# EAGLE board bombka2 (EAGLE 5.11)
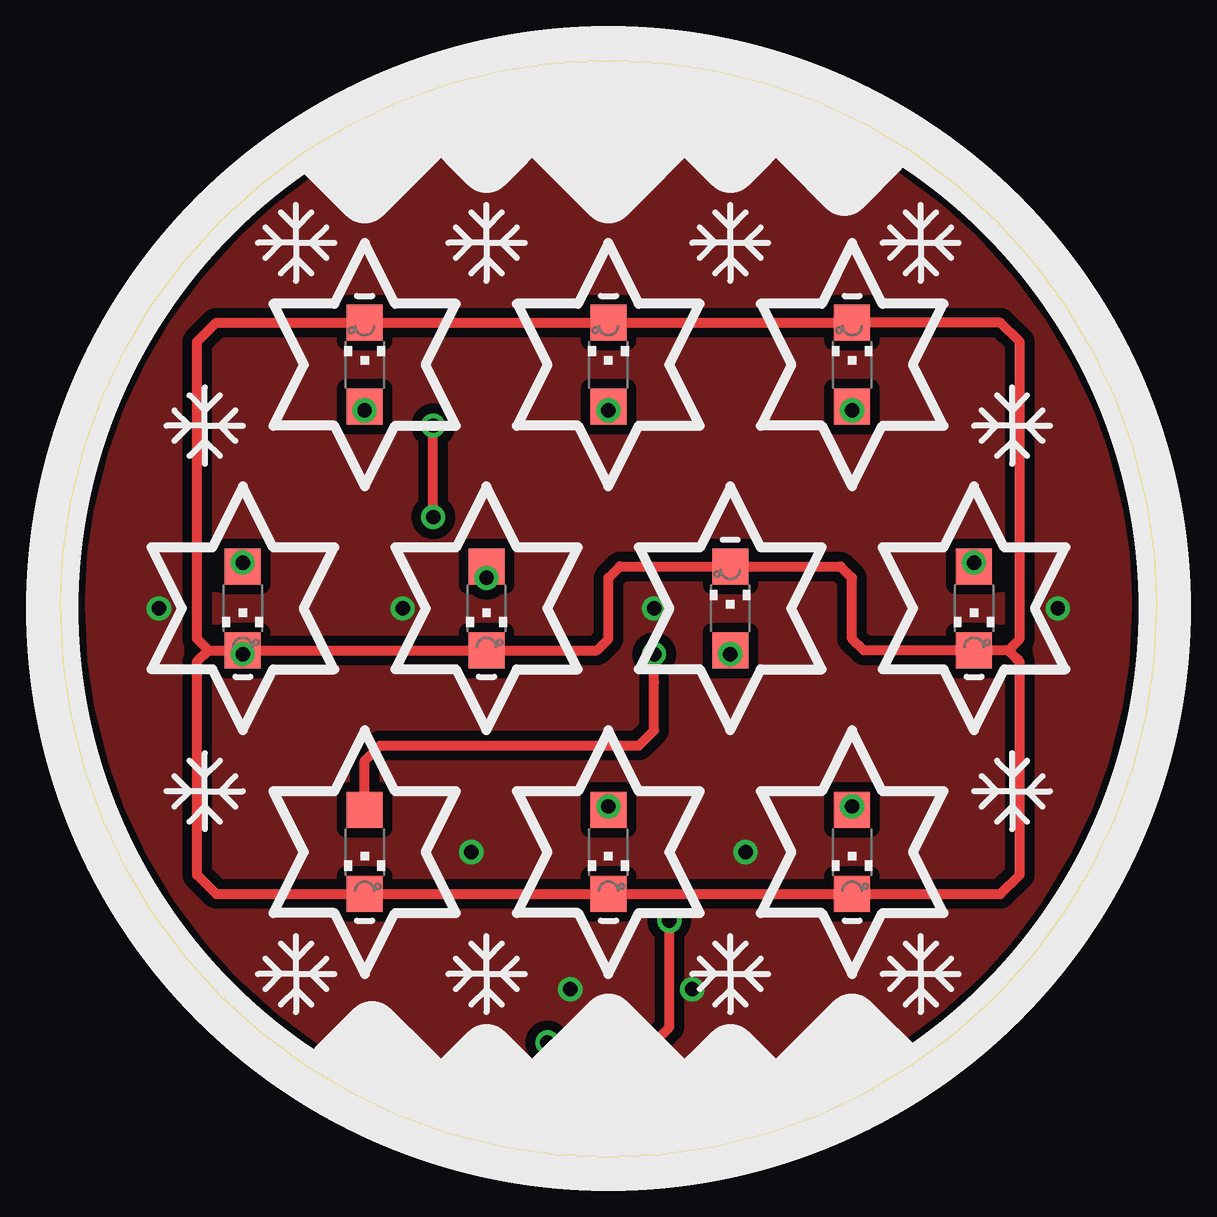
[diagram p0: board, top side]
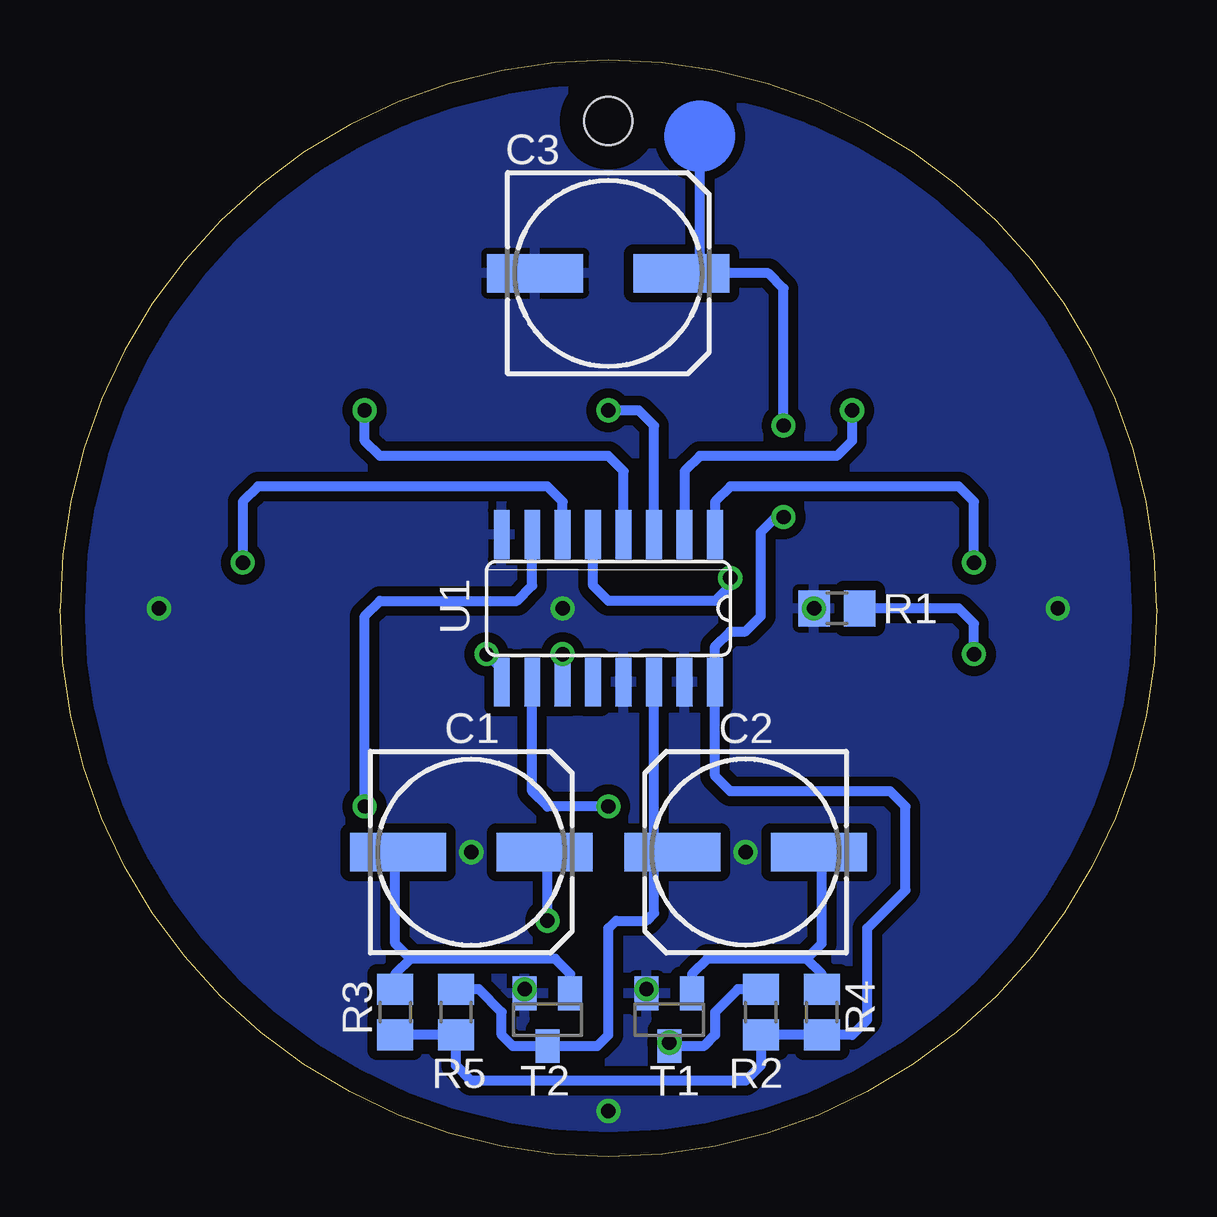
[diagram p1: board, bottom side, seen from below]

Size 45.72 x 45.72 mm. Coordinates in mm from the lower left corner, seen from the top.
Outline: 0,22.86 arc-180 45.72,22.86 arc-180 0,22.86
Copper layers (1*16): Top 0.035mm / dielectric 1.5mm / Bottom 0.035mm
Design rules "default": minimum track width 10mil, minimum drill 24mil, track to track 8mil, track to pad 8mil, pad to pad 8mil, via to via 8mil, smd to smd 8mil, copper to edge 40mil, drill to drill 8mil, minimum pad ring 10mil, minimum via ring 8mil, stop-mask expansion 4mil, vias tented up to drill 0mil, thermal gap 10mil
Holes 2 mm at 22.86,43.18

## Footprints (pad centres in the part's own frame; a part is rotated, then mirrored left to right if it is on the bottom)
153CLV-0807 = smd 4 x 1.6: + 3.05,0; - -3.05,0
CHIPLED_1206 = smd 1.5 x 1.5: A 0,-1.75; C 0,1.75
R0805 = smd 1.3 x 1.5: 1 -0.95,0; 2 0.95,0
SOT23 = smd 1 x 1.4: 1 -0.95,-1.1; 2 0.95,-1.1; 3 0,1.1
SO16 = smd 0.66 x 2.032: 1 -4.445,-3.073; 2 -3.175,-3.073; 3 -1.905,-3.073; 4 -0.635,-3.073; 5 0.635,-3.073; 6 1.905,-3.073; 7 3.175,-3.073; 8 4.445,-3.073; 9 4.445,3.073; 10 3.175,3.073; 11 1.905,3.073; 12 0.635,3.073; 13 -0.635,3.073; 14 -1.905,3.073; 15 -3.175,3.073; 16 -4.445,3.073

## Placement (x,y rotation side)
C1  [153CLV-0807]  28.57,12.7 0 bottom
C2  [153CLV-0807]  17.14,12.7 180 bottom
C3  [153CLV-0807]  22.86,36.83 0 bottom
D1  [CHIPLED_1206]  22.86,33.02 0 top
D2  [CHIPLED_1206]  12.7,33.02 0 top
D3  [CHIPLED_1206]  33.02,33.02 0 top
D4  [CHIPLED_1206]  33.02,12.7 180 top
D5  [CHIPLED_1206]  22.86,12.7 180 top
D6  [CHIPLED_1206]  7.62,22.86 180 top
D7  [CHIPLED_1206]  17.78,22.86 180 top
D8  [CHIPLED_1206]  38.1,22.86 180 top
D9  [CHIPLED_1206]  27.94,22.86 0 top
D10  [CHIPLED_1206]  12.7,12.7 180 top
R1  [R0805]  13.34,22.86 0 bottom
R2  [R0805]  16.51,6.03 270 bottom
R3  [R0805]  31.75,6.03 270 bottom
R4  [R0805]  13.97,6.03 270 bottom
R5  [R0805]  29.21,6.03 270 bottom
T1  BC847  [SOT23]  20.32,5.71 180 bottom
T2  BC847  [SOT23]  25.4,5.71 180 bottom
U1  4017D  [SO16]  22.86,22.86 180 bottom

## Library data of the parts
C1-C3 R1-R5 = rcl
D1-D10 = led
T1 T2 = transistor-npn
U1 = 40xx

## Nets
GND: C3.- R1.1 T1.2 T2.2 U1.8 U1.13 U1.15
N$1: D1.A U1.3
N$2: D2.A U1.2
N$3: D3.A U1.4
N$4: D4.A U1.7
N$5: D5.A U1.10
N$6: D6.A U1.1
N$7: D7.A U1.5
N$8: D8.A U1.6
N$9: D9.A U1.9
N$10: D10.A U1.11
N$11: D1.C D2.C D3.C D4.C D5.C D6.C D7.C D8.C D9.C D10.C R1.2
N$12: C1.+ R2.1 T1.3
N$13: C2.+ R5.1 T2.3 U1.14
N$14: C3.+ R2.2 R3.2 R4.2 R5.2 U1.16
N$15: C1.- R3.1 T2.1
N$16: C2.- R4.1 T1.1

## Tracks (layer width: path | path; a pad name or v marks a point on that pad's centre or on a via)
GND  (via drill 0.6)
  other vias: 14.29,22.86 24.77,22.86 28.57,12.7 17.14,12.7 22.86,1.9 21.27,6.98 26.35,6.98 4.13,22.86 41.59,22.86
  pour Top (isolate 0.406): 0.63,22.86 arc-90 22.86,45.09 arc-90 45.09,22.86 arc-90 22.86,0.63 arc-90
  pour Bottom (isolate 0.406): 0.63,22.86 arc-90 22.86,45.09 arc-90 45.09,22.86 arc-90 22.86,0.63 arc-90
N$1  (via drill 0.6)
  Top 0.406: v22.86,31.11 D1.A
  Bottom 0.406: U1.3 20.96,30.48 21.59,31.11 v22.86,31.11
N$2  (via drill 0.6)
  Top 0.406: D2.A v12.7,31.11
  Bottom 0.406: U1.2 19.69,28.57 19.05,29.21 13.34,29.21 12.7,29.84 v12.7,31.11
N$3  (via drill 0.6)
  Top 0.406: v33.02,31.11 D3.A
  Bottom 0.406: U1.4 22.23,28.57 22.86,29.21 32.38,29.21 33.02,29.84 v33.02,31.11
N$4  (via drill 0.6)
  Top 0.406: D4.A v33.02,14.6
  Bottom 0.406: U1.7 26.04,23.81 26.67,23.18 32.38,23.18 33.02,22.54 v33.02,14.6
N$5  (via drill 0.6)
  Top 0.406: v22.86,14.6 22.71,14.6 D5.A
  Bottom 0.406: U1.10 26.04,15.24 25.4,14.6 v22.86,14.6
N$6  (via drill 0.6)
  Top 0.406: D6.A v7.62,24.76
  Bottom 0.406: U1.1 18.41,27.3 17.78,27.94 8.25,27.94 7.62,27.3 v7.62,24.76
N$7  (via drill 0.6)
  Top 0.406: v17.78,24.13 D7.A
  Bottom 0.406: U1.5 23.5,23.81 22.86,23.18 18.41,23.18 17.78,23.81 v17.78,24.13
N$8  (via drill 0.6)
  Top 0.406: v38.1,24.76 D8.A
  Bottom 0.406: U1.6 24.77,27.3 25.4,27.94 37.47,27.94 38.1,27.3 v38.1,24.76
N$9  (via drill 0.6)
  Top 0.406: v27.94,20.95 D9.A
  Bottom 0.406: U1.9 27.41,20.42 v27.94,20.95
N$10  (via drill 0.6)
  Top 0.406: D10.A 12.7,16.51 13.34,17.14 24.13,17.14 24.77,17.78 U1.11 v24.77,20.95
  Bottom 0.406: v24.77,20.95 U1.11
N$11  (via drill 0.6)
  Top 0.406: 39.52,21.11 40.01,21.59 40.01,33.97 39.21,34.77 D3.C D1.C D2.C 6.51,34.77 5.72,33.97 5.72,21.59 6.19,21.11 | D6.C D7.C 22.38,21.11 22.86,21.59 22.86,24.13 23.34,24.61 D9.C 32.54,24.61 33.02,24.13 33.02,21.59 33.5,21.11 D8.C 39.52,21.11 | 39.52,21.11 39.84,20.8 40.01,20.64 40.01,11.75 39.21,10.95 D5.C | 6.19,21.11 D6.C | 6.19,21.11 5.72,20.64 5.72,11.75 6.51,10.95 D10.C D5.C | D6.C v7.62,20.95 | 39.69,20.95 39.53,21.11 39.52,21.11 | D5.C D4.C
  Bottom 0.406: R1.2 8.25,22.86 7.62,22.22 v7.62,20.95
N$12  (via drill 0.6)
  Top 0.406: v20.32,4.76 24.77,4.76 25.4,5.4 v25.4,9.84
  Bottom 0.406: R2.1 17.46,6.98 18.41,6.03 18.41,5.08 18.88,4.61 20.17,4.61 | 20.17,4.61 T1.3 | 20.17,4.61 v20.32,4.76 | v25.4,9.84 25.4,12.57 C1.+
N$13
  Bottom 0.406: R5.1 28.26,6.98 27.3,6.03 27.3,5.08 26.84,4.61 T2.3 23.32,4.61 22.86,5.08 22.86,9.52 22.54,9.84 21.27,9.84 20.96,10.16 20.96,12.7 | 20.96,12.7 C2.+ | 20.96,12.7 U1.14
N$14  (via drill 0.6)
  Top 0.406: v15.56,26.67 v15.56,30.48
  Bottom 0.406: R3.2 R5.2 29.21,3.81 28.57,3.17 17.14,3.17 16.51,3.81 R2.2 R4.2 12.7,5.08 12.07,5.71 12.07,9.52 10.48,11.11 10.48,14.6 11.11,15.24 17.78,15.24 18.41,15.87 U1.16 18.41,21.27 17.78,21.91 17.14,21.91 16.51,22.54 16.51,26.03 15.88,26.67 v15.56,26.67 | 19.69,36.95 C3.+ 19.05,36.83 | v15.56,30.48 15.56,36.2 16.19,36.83 19.05,36.83 | 19.05,36.83 19.05,42.54
N$15
  Bottom 0.406: T2.1 24.45,7.62 25.08,8.25 31.12,8.25 | 31.12,8.25 31.75,8.89 31.75,12.57 C1.- | R3.1 31.75,7.62 31.12,8.25
N$16
  Bottom 0.406: T1.1 19.37,7.62 18.73,8.25 14.61,8.25 | 14.61,8.25 13.97,7.62 R4.1 | 14.61,8.25 13.97,8.89 13.97,12.57 C2.-
(copper drawn outside any net)
  shapes: Bottom circle x4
